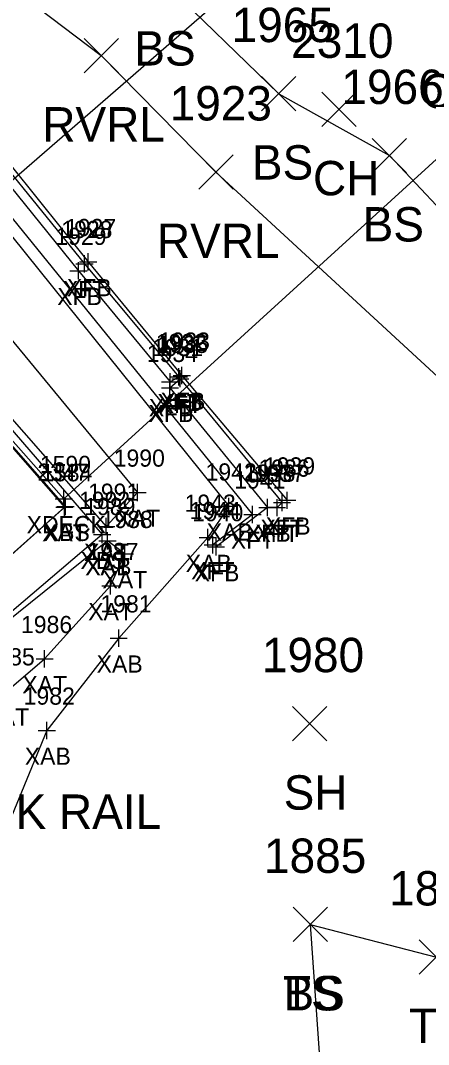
# Model space of a CAD drawing. Extents: x 1647133 to 1649138, y 411736 to 414924.
# Drawn here: x 1648853.9 to 1648877.6, y 412065.9 to 412125.5 of the extents above; entities that cross this region are included whole.
import ezdxf

# ---------------------------------------------------------------- set-up
doc = ezdxf.new("R2010")
doc.units = 0
for name, color, linetype in [('B_A', 7, 'Continuous'), ('B_I', 7, 'Continuous'), ('B_TIC', 7, 'Continuous'), ('BELB', 7, 'Continuous'), ('BFT', 7, 'Continuous'), ('BSE', 7, 'Continuous'), ('BSUBM', 7, 'Continuous'), ('L_A', 7, 'Continuous'), ('L_I', 7, 'Continuous'), ('L_TIC', 7, 'Continuous'), ('LAWE', 7, 'Continuous'), ('LELB', 7, 'Continuous'), ('R_C', 7, 'Continuous')]:
    doc.layers.add(name, color=color, linetype=linetype)

msp = doc.modelspace()

# ---------------------------------------------------------------- linework, layer by layer
at = {"layer": 'B_TIC'}
for p, q in [((1648857.573, 412111.314), (1648857.648, 412111.314)), ((1648857.793, 412111.426), (1648857.869, 412111.426)), ((1648857.231, 412110.913), (1648857.306, 412110.913)), ((1648863.069, 412104.738), (1648863.145, 412104.738)), ((1648863.069, 412104.738), (1648863.145, 412104.738)), ((1648863.149, 412104.625), (1648863.225, 412104.625)), ((1648863.242, 412104.817), (1648863.318, 412104.817)), ((1648862.547, 412104.099), (1648862.622, 412104.099)), ((1648862.547, 412104.099), (1648862.622, 412104.099)), ((1648862.562, 412104.443), (1648862.638, 412104.443)), ((1648860.666, 412098.007), (1648860.742, 412098.007)), ((1648856.37, 412097.638), (1648856.445, 412097.638)), ((1648856.37, 412097.638), (1648856.445, 412097.638)), ((1648869.065, 412097.423), (1648869.141, 412097.423)), ((1648869.366, 412097.552), (1648869.442, 412097.552)), ((1648856.405, 412097.156), (1648856.481, 412097.156)), ((1648856.466, 412097.184), (1648856.542, 412097.184)), ((1648865.965, 412097.201), (1648866.041, 412097.201)), ((1648868.212, 412097.136), (1648868.287, 412097.136)), ((1648868.212, 412097.136), (1648868.287, 412097.136)), ((1648868.774, 412097.125), (1648868.85, 412097.125)), ((1648867.347, 412096.727), (1648867.423, 412096.727)), ((1648858.602, 412095.552), (1648858.678, 412095.552)), ((1648858.847, 412096.022), (1648858.922, 412096.022)), ((1648858.847, 412096.022), (1648858.922, 412096.022)), ((1648858.91, 412095.188), (1648858.986, 412095.188)), ((1648858.91, 412095.188), (1648858.986, 412095.188)), ((1648864.747, 412095.384), (1648864.822, 412095.384)), ((1648865.037, 412094.958), (1648865.113, 412094.958)), ((1648859.919, 412094.436), (1648859.995, 412094.436)), ((1648865.226, 412094.834), (1648865.301, 412094.834)), ((1648859.091, 412092.575), (1648859.166, 412092.575)), ((1648859.565, 412089.524), (1648859.64, 412089.524)), ((1648855.258, 412088.323), (1648855.333, 412088.323)), ((1648855.384, 412084.158), (1648855.459, 412084.158))]:
    msp.add_line(p, q, dxfattribs=at)
for points in [[(1648857.569, 412110.814), (1648857.569, 412111.814)], [(1648857.79, 412110.926), (1648857.79, 412111.926)], [(1648857.069, 412111.314), (1648858.069, 412111.314)], [(1648857.227, 412110.413), (1648857.227, 412111.413)], [(1648857.29, 412111.426), (1648858.29, 412111.426)], [(1648856.727, 412110.913), (1648857.727, 412110.913)], [(1648863.066, 412104.238), (1648863.066, 412105.238)], [(1648863.066, 412104.238), (1648863.066, 412105.238)], [(1648863.146, 412104.125), (1648863.146, 412105.125)], [(1648863.239, 412104.317), (1648863.239, 412105.317)], [(1648862.543, 412103.599), (1648862.543, 412104.599)], [(1648862.543, 412103.599), (1648862.543, 412104.599)], [(1648862.559, 412103.943), (1648862.559, 412104.943)], [(1648862.566, 412104.738), (1648863.566, 412104.738)], [(1648862.566, 412104.738), (1648863.566, 412104.738)], [(1648862.646, 412104.625), (1648863.646, 412104.625)], [(1648862.739, 412104.817), (1648863.739, 412104.817)], [(1648862.043, 412104.099), (1648863.043, 412104.099)], [(1648862.043, 412104.099), (1648863.043, 412104.099)], [(1648862.059, 412104.443), (1648863.059, 412104.443)], [(1648856.366, 412097.138), (1648856.366, 412098.138)], [(1648856.366, 412097.138), (1648856.366, 412098.138)], [(1648860.163, 412098.007), (1648861.163, 412098.007)], [(1648860.663, 412097.507), (1648860.663, 412098.507)], [(1648869.363, 412097.052), (1648869.363, 412098.052)], [(1648855.866, 412097.638), (1648856.866, 412097.638)], [(1648855.866, 412097.638), (1648856.866, 412097.638)], [(1648856.402, 412096.656), (1648856.402, 412097.656)], [(1648856.463, 412096.684), (1648856.463, 412097.684)], [(1648865.962, 412096.701), (1648865.962, 412097.701)], [(1648868.208, 412096.636), (1648868.208, 412097.636)], [(1648868.208, 412096.636), (1648868.208, 412097.636)], [(1648868.562, 412097.423), (1648869.562, 412097.423)], [(1648868.771, 412096.625), (1648868.771, 412097.625)], [(1648868.863, 412097.552), (1648869.863, 412097.552)], [(1648869.062, 412096.923), (1648869.062, 412097.923)], [(1648855.902, 412097.156), (1648856.902, 412097.156)], [(1648855.963, 412097.184), (1648856.963, 412097.184)], [(1648865.462, 412097.201), (1648866.462, 412097.201)], [(1648867.344, 412096.227), (1648867.344, 412097.227)], [(1648867.708, 412097.136), (1648868.708, 412097.136)], [(1648867.708, 412097.136), (1648868.708, 412097.136)], [(1648868.271, 412097.125), (1648869.271, 412097.125)], [(1648858.843, 412095.522), (1648858.843, 412096.522)], [(1648858.843, 412095.522), (1648858.843, 412096.522)], [(1648866.844, 412096.727), (1648867.844, 412096.727)], [(1648858.099, 412095.552), (1648859.099, 412095.552)], [(1648858.343, 412096.022), (1648859.343, 412096.022)], [(1648858.343, 412096.022), (1648859.343, 412096.022)], [(1648858.599, 412095.052), (1648858.599, 412096.052)], [(1648858.907, 412094.688), (1648858.907, 412095.688)], [(1648858.907, 412094.688), (1648858.907, 412095.688)], [(1648864.743, 412094.884), (1648864.743, 412095.884)], [(1648858.407, 412095.188), (1648859.407, 412095.188)], [(1648858.407, 412095.188), (1648859.407, 412095.188)], [(1648864.243, 412095.384), (1648865.243, 412095.384)], [(1648864.534, 412094.958), (1648865.534, 412094.958)], [(1648865.034, 412094.458), (1648865.034, 412095.458)], [(1648865.222, 412094.334), (1648865.222, 412095.334)], [(1648859.416, 412094.436), (1648860.416, 412094.436)], [(1648859.916, 412093.936), (1648859.916, 412094.936)], [(1648864.722, 412094.834), (1648865.722, 412094.834)], [(1648858.587, 412092.575), (1648859.587, 412092.575)], [(1648859.087, 412092.075), (1648859.087, 412093.075)], [(1648859.561, 412089.024), (1648859.561, 412090.024)], [(1648859.061, 412089.524), (1648860.061, 412089.524)], [(1648855.254, 412087.823), (1648855.254, 412088.823)], [(1648854.754, 412088.323), (1648855.754, 412088.323)], [(1648855.38, 412083.658), (1648855.38, 412084.658)], [(1648854.88, 412084.158), (1648855.88, 412084.158)]]:
    msp.add_lwpolyline(points, dxfattribs=at)
at = {"layer": 'BELB'}
for points in [[(1648856.366, 412097.638), (1648845.782, 412109.602), (1648891.837, 412149.616), (1648923.124, 412177.419), (1648960.58, 412211.026), (1648974.892, 412224.907)], [(1648856.366, 412097.638), (1648904.081, 412141.155), (1648932.964, 412166.557), (1648970.055, 412199.522), (1648985.33, 412212.818), (1648974.892, 412224.907)]]:
    msp.add_lwpolyline(points, dxfattribs=at)
at = {"layer": 'BFT'}
for points in [[(1648850.309, 412120.73), (1648857.79, 412111.426), (1648863.239, 412104.817), (1648869.363, 412097.552)], [(1648847.819, 412119.764), (1648848.263, 412120.228), (1648867.344, 412096.727), (1648865.034, 412094.958)], [(1648849.664, 412120.263), (1648857.227, 412110.913), (1648862.559, 412104.443), (1648863.066, 412104.738)], [(1648850.132, 412120.462), (1648857.569, 412111.314), (1648863.066, 412104.738)], [(1648862.543, 412104.099), (1648863.146, 412104.625), (1648869.062, 412097.423), (1648868.771, 412097.125), (1648868.208, 412097.136)], [(1648862.543, 412104.099), (1648868.208, 412097.136), (1648865.222, 412094.834)]]:
    msp.add_lwpolyline(points, dxfattribs=at)
at = {"layer": 'BSE'}
msp.add_lwpolyline([(1648836.225, 412104.909), (1648844.312, 412112.104), (1648858.599, 412095.552), (1648850.448, 412088.61), (1648848.905, 412090.442), (1648856.463, 412097.184), (1648844.973, 412110.297), (1648837.366, 412103.687)], dxfattribs=at)
at = {"layer": 'BSUBM'}
for points in [[(1648834.098, 412112.598), (1648838.135, 412115.208), (1648847.819, 412119.764), (1648865.962, 412097.201), (1648864.743, 412095.384), (1648859.561, 412089.524), (1648855.38, 412084.158), (1648852.149, 412076.311)], [(1648834.767, 412111.771), (1648841.027, 412115.113), (1648847.311, 412117.099), (1648847.285, 412115.785), (1648846.9, 412114.694), (1648844.589, 412112.276), (1648858.843, 412096.022)], [(1648846.9, 412114.694), (1648860.663, 412098.007), (1648858.843, 412096.022)], [(1648831.501, 412103.876), (1648831.413, 412104.48), (1648835.922, 412104.951), (1648837.246, 412103.531), (1648844.963, 412110.234), (1648856.402, 412097.156), (1648848.705, 412090.291), (1648850.354, 412088.365), (1648849.848, 412084.785), (1648848.957, 412084.934), (1648849.42, 412088.003)], [(1648849.746, 412074.998), (1648853.052, 412086.444), (1648855.254, 412088.323), (1648859.087, 412092.575), (1648859.916, 412094.436), (1648858.907, 412095.188)], [(1648858.907, 412095.188), (1648850.739, 412088.617), (1648850.1, 412084.487)]]:
    msp.add_lwpolyline(points, dxfattribs=at)
at = {"layer": 'L_TIC'}
for points in [[(1648857.551, 412122.429), (1648859.551, 412124.429)], [(1648859.551, 412122.429), (1648857.551, 412124.429)], [(1648867.869, 412120.213), (1648869.869, 412122.213)], [(1648869.869, 412120.213), (1648867.869, 412122.213)], [(1648871.374, 412119.298), (1648873.374, 412121.298)], [(1648873.374, 412119.298), (1648871.374, 412121.298)], [(1648874.311, 412116.612), (1648876.311, 412118.612)], [(1648876.311, 412116.612), (1648874.311, 412118.612)], [(1648864.22, 412115.653), (1648866.22, 412117.653)], [(1648866.22, 412115.653), (1648864.22, 412117.653)], [(1648869.669, 412083.549), (1648871.669, 412085.549)], [(1648871.669, 412083.549), (1648869.669, 412085.549)], [(1648869.706, 412071.868), (1648871.706, 412073.868)], [(1648871.706, 412071.868), (1648869.706, 412073.868)], [(1648869.706, 412071.868), (1648871.706, 412073.868)], [(1648871.706, 412071.868), (1648869.706, 412073.868)], [(1648877.04, 412069.973), (1648879.04, 412071.973)], [(1648879.04, 412069.973), (1648877.04, 412071.973)]]:
    msp.add_lwpolyline(points, dxfattribs=at)
at = {"layer": 'LAWE'}
msp.add_lwpolyline([(1648837.128, 412133.097), (1648849.111, 412130.576), (1648858.551, 412123.429), (1648865.22, 412116.653), (1648885.08, 412098.314), (1648895.742, 412085.318), (1648904.966, 412074.676), (1648913.662, 412064.354), (1648932.191, 412046.181), (1648949.069, 412033.32)], dxfattribs=at)
at = {"layer": 'LELB'}
for points in [[(1648885.787, 412152.041), (1648870.49, 412148.148), (1648856.957, 412156.187), (1648842.553, 412158.499), (1648828.356, 412162.203), (1648812.843, 412166.91), (1648807.082, 412168.189), (1648801.769, 412172.895), (1648797.645, 412167.837), (1648792.644, 412160.569), (1648799.379, 412154.937), (1648809.001, 412149.8), (1648818.426, 412144.032), (1648829.711, 412141.28), (1648839.461, 412137.596), (1648848.65, 412137.378), (1648855.669, 412134.7), (1648862.03, 412127.85), (1648868.869, 412121.213), (1648875.311, 412117.612), (1648882.604, 412109.86)], [(1648870.706, 412072.868), (1648871.765, 412057.665), (1648894.095, 412039.166), (1648930.858, 412008.261)], [(1648870.706, 412072.868), (1648878.04, 412070.973), (1648905.433, 412046.074), (1648939.422, 412014.67)]]:
    msp.add_lwpolyline(points, dxfattribs=at)

# ---------------------------------------------------------------- texts
at = {"layer": 'B_A'}
for s, p in [('XFB', (1648855.987, 412108.913)), ('XFT', (1648856.314, 412109.314)), ('XFB', (1648856.55, 412109.426)), ('XFB', (1648861.318, 412102.443)), ('XFT', (1648861.81, 412102.738)), ('XFB', (1648861.825, 412102.738)), ('XFT', (1648861.89, 412102.625)), ('XFB', (1648861.999, 412102.817)), ('XFT', (1648861.287, 412102.099)), ('XFB', (1648861.303, 412102.099)), ('XAT', (1648859.368, 412096.007)), ('XDECK', (1648854.209, 412095.638)), ('XDECK', (1648854.209, 412095.638)), ('XAT', (1648855.107, 412095.156)), ('XBS', (1648855.203, 412095.184)), ('XAB', (1648864.682, 412095.201)), ('XFT', (1648867.806, 412095.423)), ('XFB', (1648868.122, 412095.552)), ('XFT', (1648866.088, 412094.727)), ('XFT', (1648866.952, 412095.136)), ('XFB', (1648866.968, 412095.136)), ('XFT', (1648867.515, 412095.125)), ('XAT', (1648857.548, 412094.022)), ('XAT', (1648857.548, 412094.022)), ('XBS', (1648857.339, 412093.552)), ('XAB', (1648863.464, 412093.384)), ('XAT', (1648857.612, 412093.188)), ('XAB', (1648857.627, 412093.188)), ('XFT', (1648863.778, 412092.958)), ('XFB', (1648863.982, 412092.834)), ('XAT', (1648858.621, 412092.436)), ('XAT', (1648857.792, 412090.575)), ('XAB', (1648858.282, 412087.524)), ('XAT', (1648853.959, 412086.323)), ('XAT', (1648851.757, 412084.444)), ('XAB', (1648854.101, 412082.158))]:
    msp.add_text(s, height=1, dxfattribs=at).set_placement(p)
at = {"layer": 'B_I'}
for s, p in [('1929', (1648855.877, 412112.413)), ('1928', (1648856.223, 412112.814)), ('1927', (1648856.443, 412112.926)), ('1931', (1648861.496, 412105.943)), ('1932', (1648861.719, 412106.238)), ('1932', (1648861.719, 412106.238)), ('1935', (1648861.799, 412106.125)), ('1933', (1648861.892, 412106.317)), ('1934', (1648861.197, 412105.599)), ('1934', (1648861.197, 412105.599)), ('1990', (1648859.273, 412099.507)), ('1590', (1648854.976, 412099.138)), ('1590', (1648854.976, 412099.138)), ('1942', (1648864.615, 412098.701)), ('1936', (1648867.688, 412098.923)), ('1939', (1648868.012, 412099.052)), ('2347', (1648854.833, 412098.684)), ('1584', (1648855.055, 412098.656)), ('1941', (1648866.281, 412098.227)), ('1938', (1648866.862, 412098.636)), ('1938', (1648866.862, 412098.636)), ('1937', (1648867.424, 412098.625)), ('1991', (1648857.78, 412097.522)), ('1991', (1648857.78, 412097.522)), ('1992', (1648857.252, 412097.052)), ('1989', (1648857.557, 412096.688)), ('1989', (1648857.557, 412096.688)), ('1943', (1648863.397, 412096.884)), ('1944', (1648863.688, 412096.458)), ('1940', (1648863.833, 412096.334)), ('1988', (1648858.57, 412095.936)), ('1987', (1648857.741, 412094.075)), ('1981', (1648858.498, 412091.024)), ('1986', (1648853.88, 412089.823)), ('1985', (1648851.705, 412087.944)), ('1982', (1648854.034, 412085.658))]:
    msp.add_text(s, height=1, dxfattribs=at).set_placement(p)
at = {"layer": 'L_A'}
for s, p in [('BS', (1648860.471, 412122.85)), ('CH', (1648877.123, 412120.367)), ('RVRL', (1648855.118, 412118.429)), ('BS', (1648867.31, 412116.213)), ('CH', (1648870.862, 412115.298)), ('BS', (1648873.752, 412112.612)), ('RVRL', (1648861.787, 412111.653)), ('SH', (1648869.157, 412079.549)), ('TS', (1648869.116, 412067.868)), ('BS', (1648869.147, 412067.868)), ('TS', (1648876.45, 412065.973))]:
    msp.add_text(s, height=2, dxfattribs=at).set_placement(p)
at = {"layer": 'L_I'}
for s, p in [('1965', (1648866.129, 412124.213)), ('2310', (1648869.594, 412123.298)), ('1966', (1648872.515, 412120.612)), ('1923', (1648862.527, 412119.653)), ('1980', (1648867.889, 412087.549)), ('1885', (1648868.013, 412075.868)), ('1885', (1648868.013, 412075.868)), ('1886', (1648875.292, 412073.973))]:
    msp.add_text(s, height=2, dxfattribs=at).set_placement(p)
at = {"layer": 'R_C'}
msp.add_text('WOOD POST W/ PLANK RAIL', height=2, dxfattribs=at).set_placement((1648825.182, 412078.432))

doc.saveas('drawing.dxf')
